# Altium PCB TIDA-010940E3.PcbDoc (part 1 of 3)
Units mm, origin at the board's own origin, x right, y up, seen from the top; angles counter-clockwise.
Board outline 71.12 x 63.5 mm, 2 copper layers (Top Layer, Bottom Layer), stack 1.382 mm thick; 136 components, 118 nets, 421 pads, 150 vias.
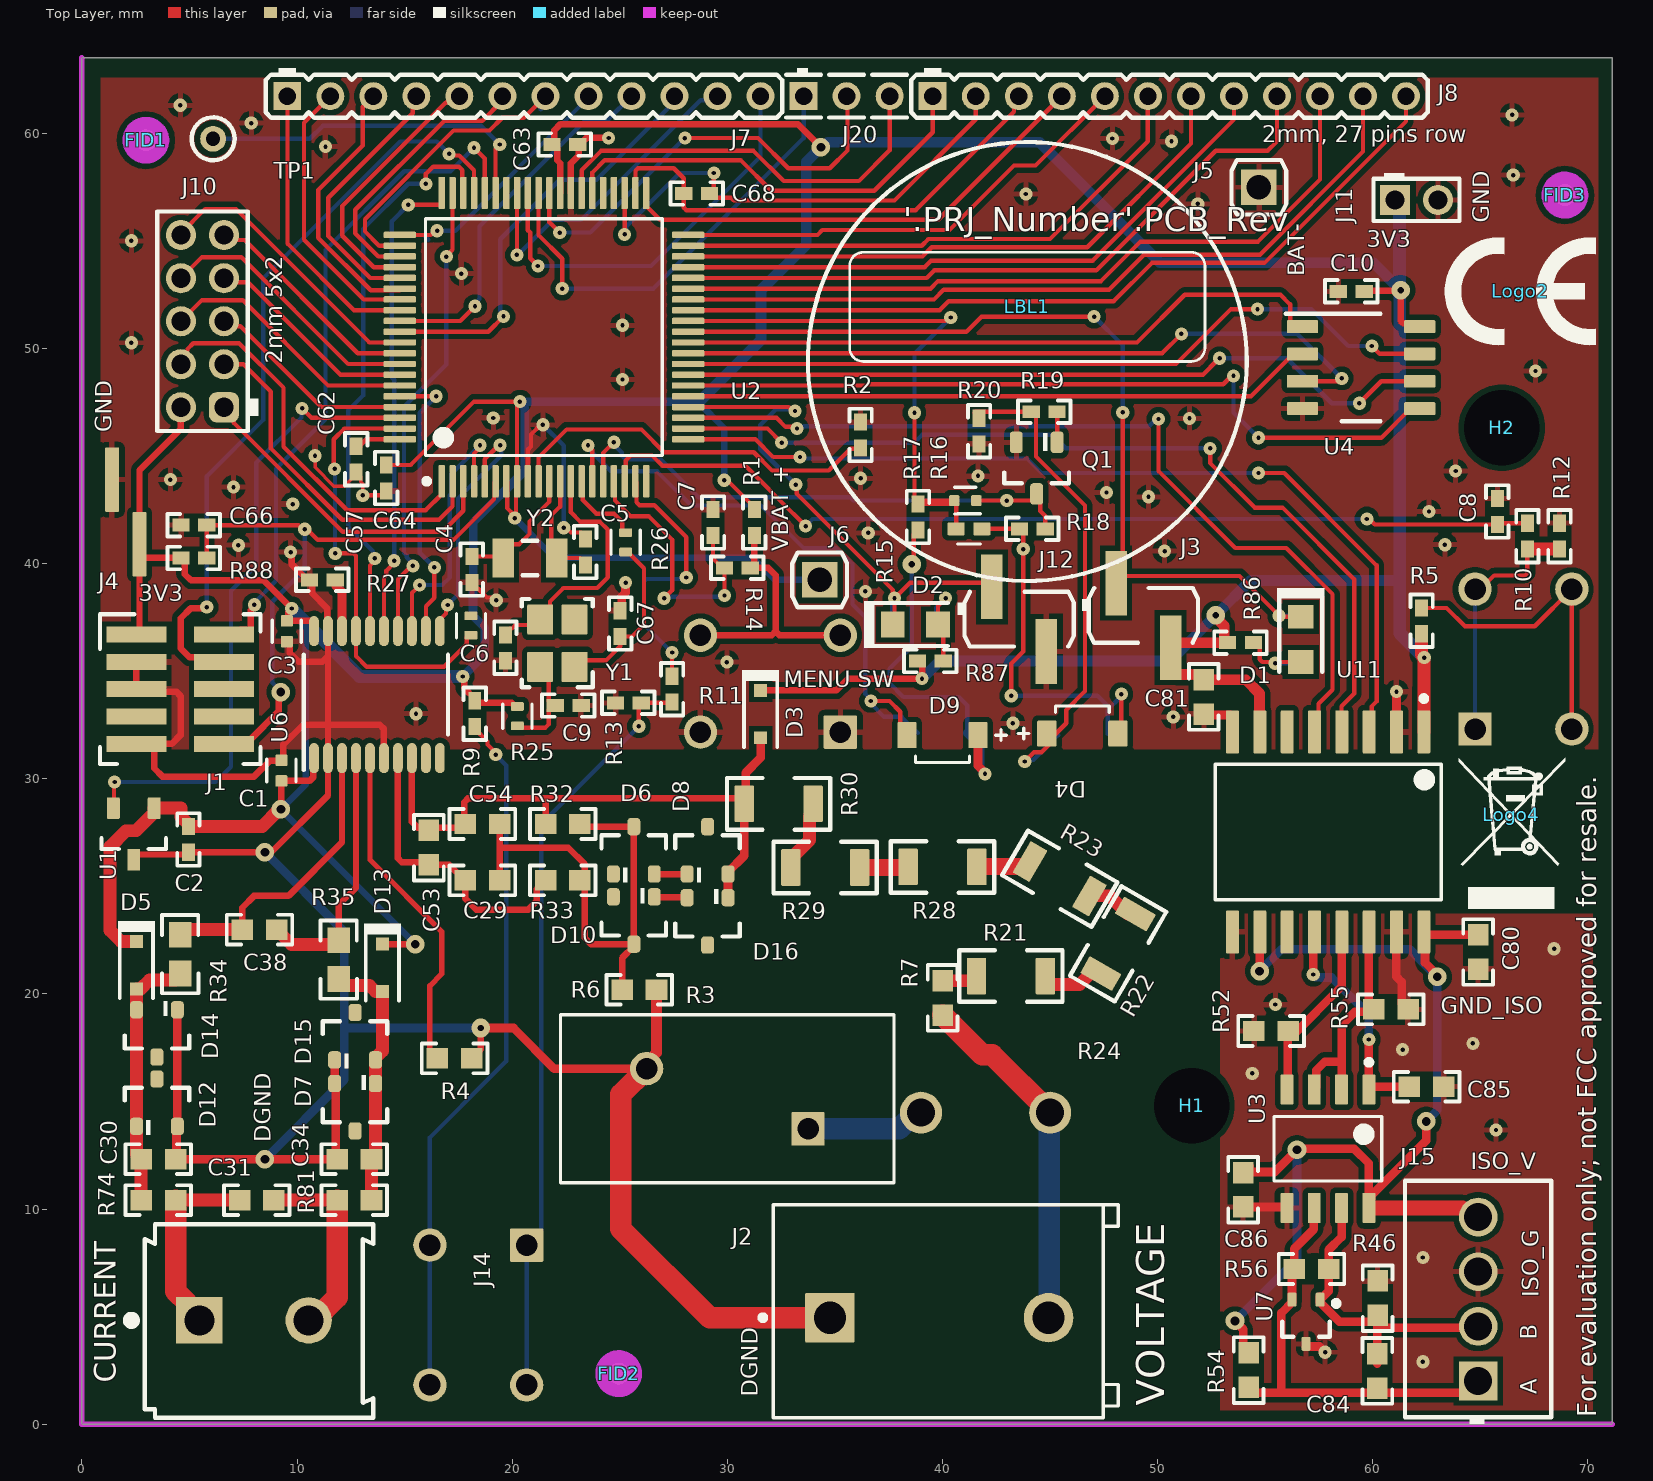
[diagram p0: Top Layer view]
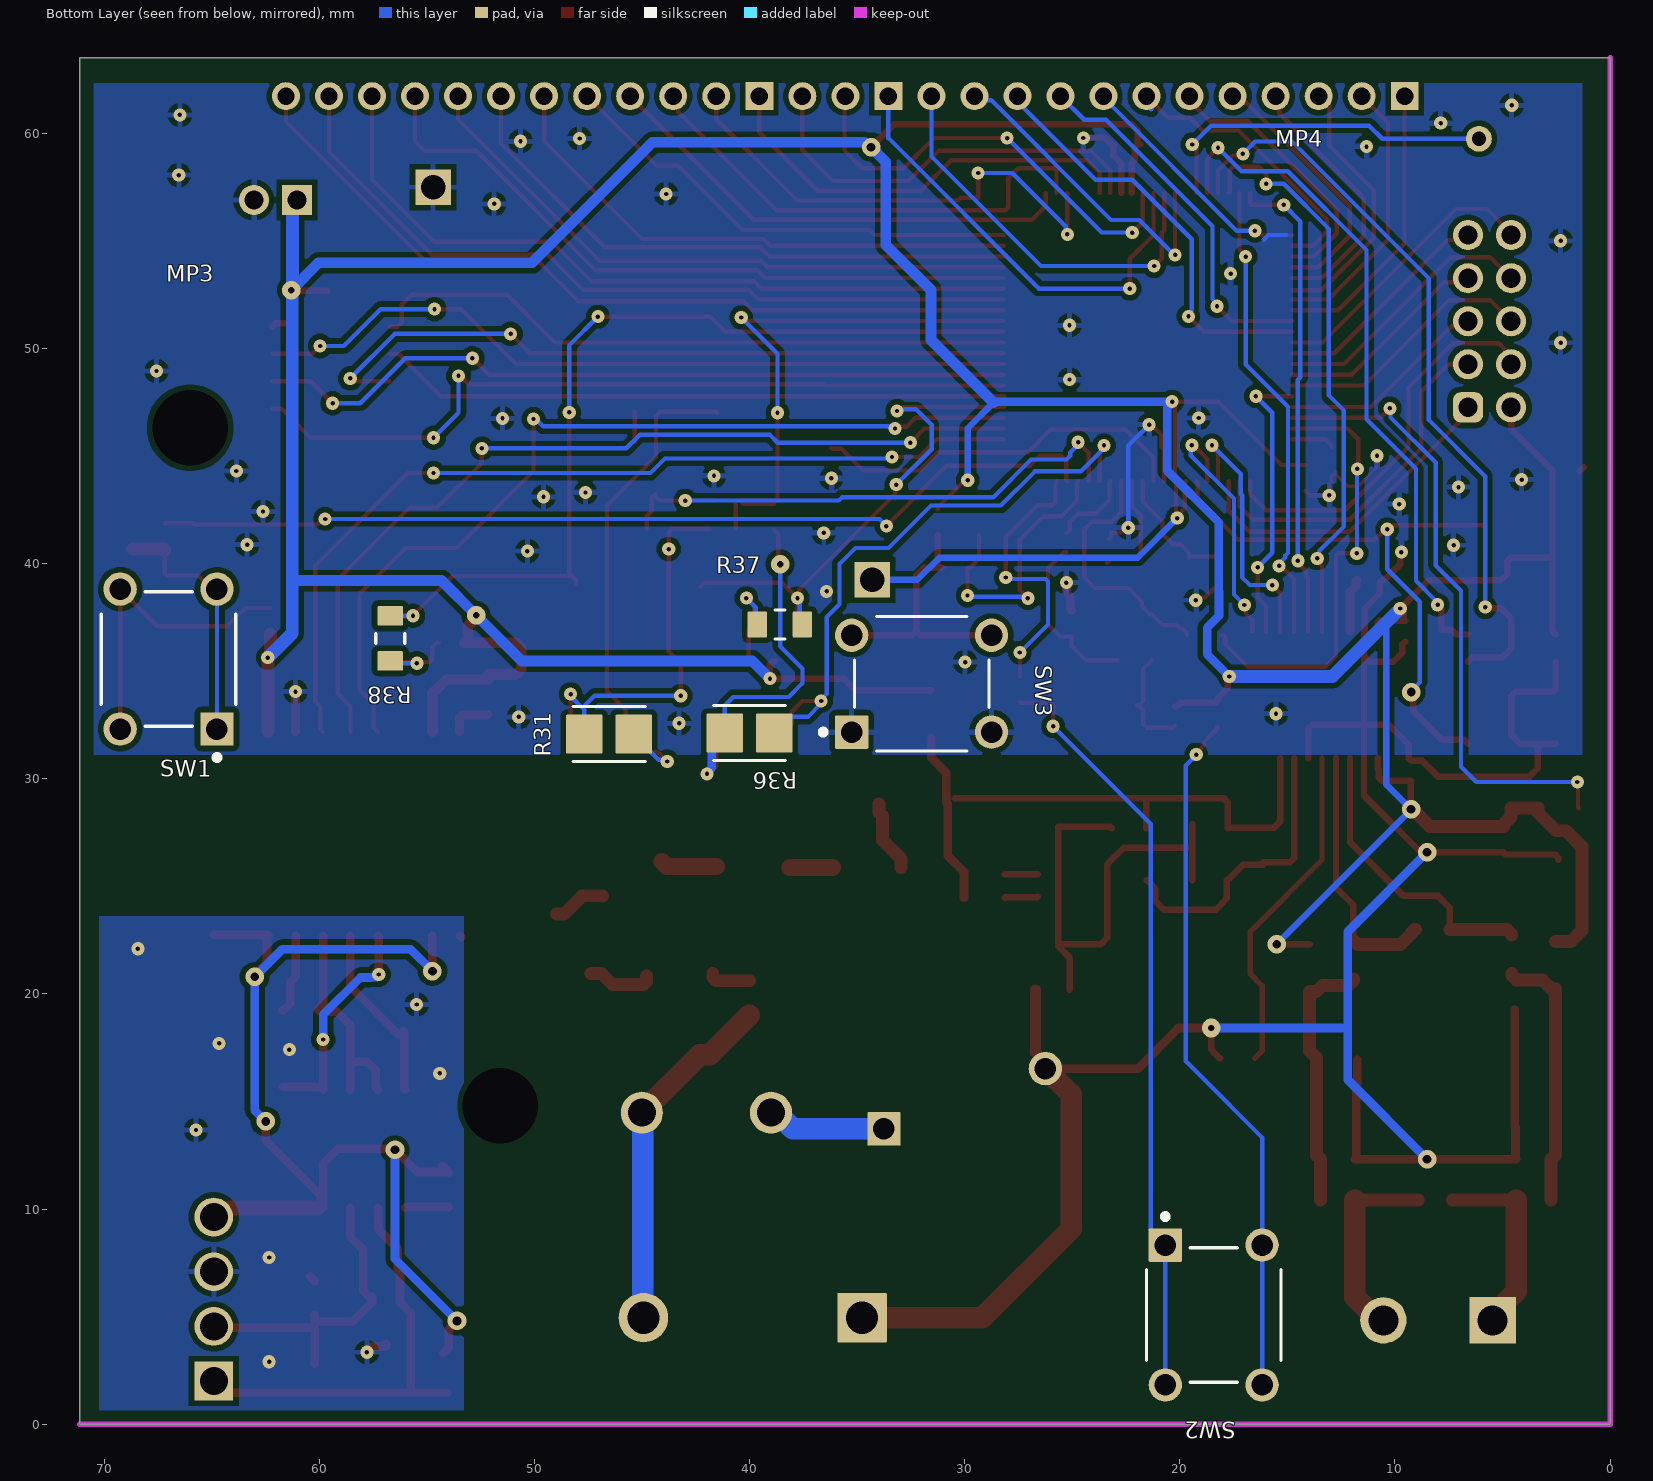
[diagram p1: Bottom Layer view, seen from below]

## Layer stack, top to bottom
Top Solder: solder mask 0.0102, Solder Resist, Dk 3.5
Top Layer: signal copper 0.0356
Dielectric 2: core 0.9906, Composite dielectric, Dk 4.8
Dielectric2: core 0.32, Composite dielectric, Dk 4.8
Bottom Layer: signal copper 0.0356
Bottom Solder: solder mask 0.0102, Solder Resist, Dk 3.5

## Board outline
0,0 0,63.5 71.12,63.5 71.12,0

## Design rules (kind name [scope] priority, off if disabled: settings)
AcuteAngle [All] p1: minimum=4.50000000000000E+0001 checktracksonly=FALSE
AssemblyTestPointUsage [All] p1: valid=2
BoardOutlineClearance BoardOutlineClearance_MountingHoles [OnCopper and InComponentClass('Mounting Holes')] p1: gap=1 ignorepadtopadclearanceinfootprint=FALSE
BoardOutlineClearance BoardOutlineClearance_Poly [OnCopper and IsPoly] p2: gap=0.635 ignorepadtopadclearanceinfootprint=FALSE
BoardOutlineClearance [OnCopper and Not InComponentClass('Logo') and not InComponentClass('FiducialMark') and not InRegion(1000,500,4000,800) and not InPoly] p3: gap=1.016 ignorepadtopadclearanceinfootprint=FALSE
Clearance Clearance_Keepouts [((IsTrack Or IsArc) And Not InPoly) And IsFree and IsKeepOut vs ((IsTrack Or IsArc) And Not InPoly) And IsFree and IsKeepOut] p1: gap=0 ignorepadtopadclearanceinfootprint=FALSE
Clearance Clearance_Poly [InPolygon] p2: gap=0.254 ignorepadtopadclearanceinfootprint=TRUE
Clearance Clearance_FiducialMark [IsKeepOut and InComponentClass('FiducialMark') vs IsPad and InComponentClass('FiducialMark')] p3: gap=0 ignorepadtopadclearanceinfootprint=FALSE
Clearance [All] p4: gap=0.18 ignorepadtopadclearanceinfootprint=TRUE
ComponentClearance ComponentClearance_BottomHW [All vs InComponentClass('Bottom Side Components')] p1: gap=0 collisioncheckmode=3 verticalgap=0 showdistances=FALSE
ComponentClearance ComponentClearance_Shunt [InComponentClass('Header') vs InComponentClass('Shunt')] p2: gap=0 collisioncheckmode=3 verticalgap=0 showdistances=FALSE
ComponentClearance ComponentClearance_MountingHoles_FiducialMarks [InComponentClass('Mounting Holes') vs InComponentClass('FiducialMark')] p3: gap=1.27 collisioncheckmode=3 verticalgap=0.254 showdistances=FALSE
ComponentClearance ComponentClearance_Logo [InComponentClass('Logo')] p4: gap=0.762 collisioncheckmode=3 verticalgap=0.254 showdistances=FALSE
ComponentClearance ComponentClearance_ScrewToNut [(HasFootprint('NY PMS 440 0025 PH')) vs (HasFootprint('Keystone_1902C'))] p5: gap=0.127 collisioncheckmode=3 verticalgap=0.254 showdistances=FALSE
ComponentClearance ComponentClearance_MountingHoles [InComponentClass('Mounting Holes')] p6: gap=2.54 collisioncheckmode=3 verticalgap=2540 showdistances=FALSE
ComponentClearance ComponentClearance_SmallPassives [HasFootprint('0201*') or HasFootprint('0402*') or HasFootprint('0508') or HasFootprint('0603*') or HasFootprint('0612') or HasFootprint('0805*') or HasFootprint('0815*') or HasFootprint('0830*') or HasFootprint('1206*') or HasFootprint('1210*') or HasFootprint('1808*') or HasFootprint('1812*') or HasFootprint('1825*') or HasFootprint('2010*') or HasFootprint('2220*') or HasFootprint('2225*') or HasFootprint('2512*') or HasFootprint('2728*') or HasFootprint('3518*') vs HasFootprint('0201*') or HasFootprint('0402*') or HasFootprint('0508') or HasFootprint('0603*') or HasFootprint('0612') or HasFootprint('0805*') or HasFootprint('0815*') or HasFootprint('0830*') or HasFootprint('1206*') or HasFootprint('1210*') or HasFootprint('1808*') or HasFootprint('1812*') or HasFootprint('1825*') or HasFootprint('2010*') or HasFootprint('2220*') or HasFootprint('2225*') or HasFootprint('2512*') or HasFootprint('2728*') or HasFootprint('3518*')] p7: gap=0.38 collisioncheckmode=3 verticalgap=0.254 showdistances=FALSE
ComponentClearance ComponentClearance_THtoSMT [IsThruComponent vs InComponentClass('Shunt')] p8: gap=0 collisioncheckmode=3 verticalgap=1 showdistances=FALSE
ComponentClearance ComponentClearance_LCDtoSMT [IsThruComponent vs InComponentClass('Shunt')] p9: gap=0 collisioncheckmode=3 verticalgap=1 showdistances=FALSE
ComponentClearance ComponentClearance_THtoTH [IsThruComponent vs IsThruComponent] p10: gap=0.508 collisioncheckmode=3 verticalgap=0.762 showdistances=FALSE
ComponentClearance [All] p11: gap=0.508 collisioncheckmode=3 verticalgap=0.254 showdistances=FALSE
DiffPairsRouting [All] p1: maxlimit=2.54 minlimit=0.254 mostfreqgap=0.254 toplayer_minwidth=0.381 toplayer_maxwidth=0.381 toplayer_prefwidth=0.381 bottomlayer_minwidth=0.381 bottomlayer_maxwidth=0.381 bottomlayer_prefwidth=0.381 maxuncoupledlength=25.4
FabricationTestPointUsage TestPointUsage [All] p1: valid=2 allowmultiple=FALSE
FabricationTestpoint Testpoint [All] p1: side=3 testpointundercomponent=TRUE minsize=1.016 maxsize=2.54 preferedsize=1.524 minholesize=0 maxholesize=1.016 preferedholesize=0.813 testpointgrid=0.025 allowsidetop=TRUE allowsidebottom=TRUE usegrid=TRUE gridtolerance=0
FanoutControl Fanout_LCC [IsLCC] p1: bgadir=Out bgaviamode=Centered fanoutstyle=Auto fanoutdirection=Alternating viagrid=0.025 // Fanout_LCC (Default Rule)
FanoutControl Fanout_BGA [IsBGA] p2: bgadir=Out bgaviamode=Centered fanoutstyle=Auto fanoutdirection=Alternating viagrid=0.025 // Fanout_BGA (Default Rule)
FanoutControl Fanout_Default [All] p4: bgadir=Out bgaviamode=Centered fanoutstyle=Auto fanoutdirection=Alternating viagrid=0.025 // Fanout_Default (Default Rule)
FanoutControl Fanout_Small [(CompPinCount < 5)] p5: bgadir=Out bgaviamode=Centered fanoutstyle=Auto fanoutdirection=OutThenIn viagrid=0.025 // Fanout_Small (Default Rule)
Height [All] p1: minheight=0 maxheight=29 prefheight=12.7
HoleSize [All] p1: absolutevalues=TRUE maxlimit=6.375 minlimit=0.2 maxpercent=80.000 minpercent=20.000
MinimumAnnularRing MinimumAnnularRing_ThermalPadVias [IsVia and InAnyComponent] p1: minimumring=0.15
MinimumAnnularRing [All] p2: minimumring=0.188
MinimumSolderMaskSliver MinimumSolderMaskSliver_Logo [InComponentClass('Logo') vs InComponentClass('Logo')] p1: minsoldermaskwidth=0.018
MinimumSolderMaskSliver [All] p2: minsoldermaskwidth=0.094
PlaneConnect [All] p1: pad.planeconnectstyle=Relief pad.reliefexpansion=0.254 pad.reliefentries=4 pad.reliefconductorwidth=0.254 pad.reliefairgap=0.254 via.planeconnectstyle=Direct via.reliefexpansion=0.254 via.reliefentries=4 via.reliefconductorwidth=0.254 via.reliefairgap=0.254
PolygonConnect PolygonConnect_largePoly [All vs IsNamedPolygon('TOP_LAYER_DGNDA_P032') or IsNamedPolygon('BOTTOM_LAYER_DGNDA_P034')   or IsNamedPolygon('TOP_LAYER_HGNDB_P040')     or IsNamedPolygon('BOTTOM_LAYER_HGNDB_P042')   or IsNamedPolygon('TOP_LAYER_DGNDB_P033') or IsNamedPolygon('BOTTOM_LAYER_DGNDB_P035')] p1: thpad.connectstyle=Relief thpad.reliefconductorwidth=0.254 thpad.reliefentries=4 thpad.polygonreliefangle="90 Angle" thpad.airgapwidth=0.254 smdpad.connectstyle=Relief smdpad.reliefconductorwidth=0.254 smdpad.reliefentries=4 smdpad.polygonreliefangle="90 Angle" smdpad.airgapwidth=0.254 via.connectstyle=Direct via.reliefconductorwidth=0.254 via.reliefentries=4 via.polygonreliefangle="90 Angle" via.airgapwidth=0.254
PolygonConnect PolygonConnect_smallHGNDpoly [All vs IsPolygon and InNet('HGNDA')  or  IsNamedPolygon('TOP_LAYER_HGNDB_P024') or IsNamedPolygon('TOP_LAYER_HGNDB_P037')  or IsNamedPolygon('TOP_LAYER_HGNDB_P039')  or IsNamedPolygon('BOTTOM_LAYER_HGNDB_P043')] p2: connectstyle=Direct reliefconductorwidth=0.254 reliefentries=4 polygonreliefangle="90 Angle" airgapwidth=0.254
PolygonConnect PolygonConnect_DVDDpoly [All vs IsNamedPolygon('TOP_LAYER_ADC_DVDDA_P029') or IsNamedPolygon('TOP_LAYER_ADC_DVDDB_P029')] p3: connectstyle=Direct reliefconductorwidth=0.254 reliefentries=4 polygonreliefangle="90 Angle" airgapwidth=0.254
PolygonConnect [All] p4: connectstyle=Relief reliefconductorwidth=0.254 reliefentries=4 polygonreliefangle="90 Angle" airgapwidth=0.254
RoutingVias ThermalPadVias [IsVia and InAnyComponent] p1: holewidth=0.2 width=0.5 viastyle="Through Hole" minholewidth=0.2 minwidth=0.5 maxholewidth=0.33 maxwidth=0.6
RoutingVias [All] p2: holewidth=0.406 width=0.864 viastyle="Through Hole" minholewidth=0.2 minwidth=0.61 maxholewidth=1.016 maxwidth=1.651
SilkToBoardRegionClearance [Not ((IsComment or IsDesignator) And (Hide <> 'False')) and not InRegion(1000,500,4000,800)] p1:
SilkToSilkClearance SilkToSilkClearance_Pb-FreeLogo [(HasFootprint('Pb-Free_Overlay_Medium') OR HasFootprint('Pb-Free_Overlay_Small')) vs (HasFootprint('Pb-Free_Overlay_Medium') OR HasFootprint('Pb-Free_Overlay_Small'))] p1: silktosilkclearance=0
SilkToSilkClearance [All] p2: silktosilkclearance=0.1
SilkToSolderMaskClearance SilkToComponentPadClearance [(IsPad or IsFill or IsRegion) and InAnycomponent] p1: minsilkscreentomaskgap=0.12 clearancetoexposedcopper=TRUE
SilkToSolderMaskClearance "Silk to Solder Mask Opening" [All] p2: minsilkscreentomaskgap=0.1 clearancetoexposedcopper=FALSE
SolderMaskExpansion [All] p1: expansion=0.05 istentingtop=FALSE
SupplyNets "Schematic Supply Nets_3" [InNet('VCC_ISO_RS')] p1: voltage=0.000
SupplyNets "Schematic Supply Nets_2" [InNet('GND_ISO_RS')] p2: voltage=0.000
SupplyNets "Schematic Supply Nets_1" [InNet('DGND')] p3: voltage=0.000
SupplyNets "Schematic Supply Nets" [InNet('DVDD')] p4: voltage=0.000
UnRoutedNet [All] p1: checkbadconnections=TRUE
Width [All] p1: maxlimit=2.54 minlimit=0.152 preferedwidth=0.254 checkconnectedcopper=TRUE
13 further rules are at their usual default settings.

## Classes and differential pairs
component class TIDA-010940E3-Interfaces: C80 C81 C84 C85 C86 D4 D9 J3 J12 J15 Q1 R15 R16 R17 R18 R19 R20 R31 R36 R46 R52 R54 R55 R56 U3 U7 U11
component class TIDA-010940E3-1P_ADS131M03: C1 C3 C29 C30 C31 C34 C38 C53 C54 C57 D3 D5 D6 D7 D8 D10 D12 D13 D14 D15 D16 J2 J14 R3 R4 R6 R7 R21 R22 R23 R24 R28 R29 R30 R32 R33 R34 R35 R74 R81 U6
component class TIDA-010940E3-Hardware: !PCB1 FID1 FID2 FID3 H1 H2 LBL1 Logo2 Logo3 Logo4 MP1 MP2 MP3 MP4 ZZ1 ZZ2 ZZ3 ZZ4
component class Label: LBL1
component class FiducialMark: FID1 FID2 FID3
component class TIDA-010940E3-M0L228_80p: C2 C4 C5 C6 C7 C8 C9 C10 C62 C63 C64 C66 C67 C68 D1 D2 J1 J4 J5 J6 J7 J8 J10 J11 J20 R1 R2 R5 R9 R10 R11 R12 R13 R14 R25 R26 R27 R37 R38 R86 R87 R88 SW1 SW2 SW3 TP1 U1 U2 U4 Y1 Y2
component class AssemblyNote: C10A C11A C12A C13A ZZ1 ZZ2 ZZ3 ZZ4
component class Header: J3 J4 J5 J6 J7 J8 J10 J11 J12 J20

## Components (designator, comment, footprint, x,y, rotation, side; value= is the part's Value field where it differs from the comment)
C1 "GMC04X7R105K10NT" FP-GMC04X7R105K10NT_0402-MFG 9.273,30.378 r270 top value=1µF
C2 "GRM155R71E104KE14D" 0402 4.953,27.178 r270 top value=0.1uF
C3 "GMC04X7R105K10NT" FP-GMC04X7R105K10NT_0402-MFG 9.525,36.855 r90 top value=1µF
C4 "GRM1555C1H220JA01D" 0402 18.125,39.725 r90 top value=22pF
C5 "GRM1555C1H220JA01D" 0402 23.4,40.539 r270 top value=22pF
C6 "GRM1555C1H150JA01D" 0402 19.685,36.084 r270 top value=15pF
C7 "0402YC101KAT2A" 0402 29.337,41.91 r90 top value=100pF
C8 "0402YC101KAT2A" 0402 65.786,42.418 r90 top value=100pF
C9 "GRM155R61C474KE01" 0402 22.606,33.401 r0 top value=0.47uF
C10 "GRM155R71E104KE14D" 0402 58.997,52.652 r180 top value=0.1uF
C29 "GRM188R71C333KA01D" 0603 18.617,25.273 r180 top value=0.033uF
C30 "GRM188R71C333KA01D" 0603 3.556,12.319 r0 top value=0.033uF
C31 "06035C104KAT2A" 0603 8.128,10.414 r0 top value=0.1uF
C34 "GRM188R71C333KA01D" 0603 12.662,12.319 r0 top value=0.033uF
C38 "GRM188R71C333KA01D" 0603 8.255,22.987 r0 top value=0.033uF
C53 "C0603C472J1GAC7867" 0603 16.129,26.797 r270 top value=4700pF
C54 "GRM188R71C333KA01D" 0603 18.617,27.896 r0 top value=0.033uF
C57 "CL05B224KO5NNNC" 0402 11.176,39.243 r0 top value=0.22uF
C62 "GRM155R61C474KE01" 0402 12.75,44.85 r90 top value=0.47uF
C63 "GRM155R61A106ME11D" 0402 22.45,59.475 r180 top value=10uF
C64 "GRM155R61E105KE11D" 0402 14.149,43.978 r270 top value=1uF
C66 "GRM155R61A102KA01D" 0402 5.207,41.783 r180 top value=1000pF
C67 "GRM1555C1H150JA01D" 0402 25.019,37.211 r90 top value=15pF
C68 "GRM155R61C474KE01" 0402 28.575,57.2 r0 top value=0.47uF
C80 "C0603X104K3RACTU" 0603 64.897,21.946 r270 top value=0.1uF
C81 "C0603X104K3RACTU" 0603 52.142,33.801 r270 top value=0.1uF
C84 "CGA3E2C0G1H100D080AA" 0603 60.209,2.477 r90 top value=10pF
C85 "CGA3E2C0G1H100D080AA" 0603 62.5,15.685 r180 top value=10pF
C86 "CGA3E2X8R1E104K080AA" 0603 53.975,10.897 r270 top value=0.1uF
D1 "150080VS75000" WL-SMCW_Green_0805 56.65,36.475 r270 top value="Bright Green"
D2 "150080VS75000" WL-SMCW_Green_0805 38.745,37.166 r0 top value="Bright Green"
D3 "BAT54HT1G" SOD-323 31.547,33.002 r270 top value=30V
D4 "VSMY2853SLX01" FP-VSMY2853SLX01_SMT_LED_2MM30_2MM55-MFG 46.5,32 r180 top
D5 "BAT54HT1G" SOD-323 2.54,21.336 r270 top value=30V
D6 "BAV199-TP" SOT-23L 25.654,26.67 r90 top value=70V
D7 "BAV199-TP" SOT-23L 12.7,14.732 r270 top value=70V
D8 "BAV199-TP" SOT-23L 29.083,26.67 r90 top value=70V
D9 "VSMY2853SLX01" FP-VSMY2853SLX01_SMT_LED_2MM30_2MM55-MFG 40,32.125 r0 top
D10 "BAV199-TP" SOT-23L 25.654,23.411 r270 top value=70V
D12 "BAV199-TP" SOT-23L 3.49,14.943 r90 top value=70V
D13 "BAT54HT1G" SOD-323 13.97,21.209 r270 top value=30V
D14 "BAV199-TP" SOT-23L 3.49,18.161 r270 top value=70V
D15 "BAV199-TP" SOT-23L 12.7,18.034 r90 top value=70V
D16 "BAV199-TP" SOT-23L 29.083,23.368 r270 top value=70V
FID1 "Fiducial" Fiducial10-20 2.975,59.675 r0 top
FID2 "Fiducial" Fiducial10-20 24.95,2.35 r0 top
FID3 "Fiducial" Fiducial10-20 68.925,57.125 r90 top
H1 "3.5 MM HOLE" 3_5MM_HOLE 51.583,14.806 r0 top
H2 "3.5 MM HOLE" 3_5MM_HOLE 65.994,46.307 r0 top locked
J1 "FTSH-105-01-L-DV-K" Samtec_FTSH-105-01-x-DV-K 4.572,34.163 r0 top
J2 "691216610002" FP-691216610002_TERM_BLK_2-MFG 40.15,5.25 r0 top
J3 "61000218321" Wurth_61000218321 49.336,37.592 r0 top
J4 "M50-3630242" Harwin_M50-3630242 2.045,42.4 r0 top
J5 "61300111121" WURTH_61300111121 54.704,57.489 r0 top
J6 "61300111121" WURTH_61300111121 34.29,39.242 r0 top
J7 "M22-2511205" Harwin_M22-2511205 20.546,61.722 r0 top
J8 "M22-2511205" Harwin_M22-2511205 50.546,61.722 r0 top
J10 "MTMM-105-15-L-D-150" Samtec_MTMM-105-15-x-D-150 5.604,51.262 r180 top
J11 "TMM-102-01-F-S" Samtec_TMM-102-01-F-S 62.031,56.898 r0 top
J12 "61000218321" Wurth_61000218321 43.561,37.413 r0 top
J14 "282841-2" TEC_282841-2 8.001,4.826 r0 top
J15 "OSTVN04A150" On-Shore_OSTVN04A150 64.897,5.817 r90 top
J20 "PTT-103-01-L-S" Samtec_PTT-103-01-x-S 35.543,61.722 r0 top
LBL1 "THT-14-423-10" Label_650x200 43.942,51.929 r0 top
Logo2 "CE Mark" CE_Mark_5mm 66.85,52.65 r0 top
Logo3 "FCC disclaimer" FCC_disclaimer 79.75,-3.975 r90 top
Logo4 "WEEE logo" WEEE_Minimum 66.425,28.325 r0 top
MP1 "SJ5076" FP-SJ5076_BUMPER_CYLIN-MFG -9.275,8.4 r180 bottom
MP2 "SJ5076" FP-SJ5076_BUMPER_CYLIN-MFG 80.425,8.4 r180 bottom
MP3 "SJ5076" FP-SJ5076_BUMPER_CYLIN-MFG 60.356,51.607 r180 bottom
MP4 "SJ5076" FP-SJ5076_BUMPER_CYLIN-MFG 11.375,54.752 r180 bottom
Q1 "BC848CLT1G" SOT-23 44.377,44.436 r270 top value="30 V"
R1 "RC0402FR-07220KL" 0402 31.256,41.909 r90 top value=220k
R2 "RG1005P-104-B-T5" 0402 36.195,45.974 r270 top value=100k
R3 "B72214S2461K101" FP-B72214S2461K101_RADIAL-MFG 30,15.125 r180 top
R4 "ERJ-3GEY0R00V" 0603 17.325,17 r180 top value=0
R5 "ERJ-2RKF1002X" 0402 62.267,37.338 r270 top value=10.0k
R6 "ERJ-3GEY0R00V" 0603 25.908,20.193 r180 top value=0
R7 "ERJ-3GEY0R00V" 0603 40.005,19.812 r90 top value=0
R9 "ERJ-2RKF1002X" 0402 18.26,33.02 r90 top value=10.0k
R10 "RC0402FR-072K2L" 0402 67.183,41.275 r90 top value=2.20k
R11 "RC0402FR-072K2L" 0402 27.432,34.163 r90 top value=2.20k
R12 "CRCW04024M70JNED" 0402 68.674,41.275 r270 top value=4.7Meg
R13 "CRCW04024M70JNED" 0402 25.401,33.528 r0 top value=4.7Meg
R14 "CRCW04021K00JNED" 0402 30.466,39.8 r180 top value=1.0k
R15 "CR0402-10W-000T" FP-CR0402-10W-000T_0402-MFG 41.233,41.614 r180 top value=0uΩ
R16 "ERA-2ARB8061X" FP-ERA-2ARB8061X_0402-MFG 41.058,42.926 r180 top value=8.06k
R17 "RC0402FR-07820RL" 0402 38.862,42.164 r90 top value=820
R18 "RC0402FR-071KL" 0402 44.177,41.614 r180 top value=1.00k
R19 "ERJ-2RKF2200X" 0402 44.727,47.053 r180 top value=220
R20 "CRCW0402820RJNED" 0402 41.7,46.15 r90 top value=820
R21 "TNPV1206330KBEEN" TNPV1206 43.18,20.828 r180 top value=330k
R22 "TNPV1206330KBEEN" TNPV1206 48.163,22.325 r240 top value=330k
R23 "TNPV1206330KBEEN" TNPV1206 45.45,25.35 r150 top value=330k
R24 "AC05000004700JAC00" AC05_Vert 45,14.478 r180 top value=470
R25 "0" FP-5113_0402-MFG 20.24,32.906 r90 top
R26 "0" FP-5113_0402-MFG 25.273,40.988 r90 top
R27 "0" FP-5113_0402-MFG 18.082,37.119 r270 top
R28 "TNPV1206330KBEEN" TNPV1206 40,25.9 r0 top value=330k
R29 "TNPV1206330KBEEN" TNPV1206 34.55,25.875 r0 top value=330k
R30 "TNPV1206330KBEEN" TNPV1206 32.385,28.829 r180 top value=330k
R31 "PMR18EZPJ000" FP-PMR18EZPJ000_1206-MFG 46.525,32.075 r0 bottom value=0
R32 "RC0603FR-071KL" 0603 22.352,27.896 r180 top value=1.00k
R33 "RC0603FR-071KL" 0603 22.35,25.275 r180 top value=1.00k
R34 "RC0603FR-071KL" 0603M 4.572,21.844 r90 top value=1.00k
R35 "RC0603FR-071KL" 0603M 11.938,21.59 r90 top value=1.00k
R36 "PMR18EZPJ000" FP-PMR18EZPJ000_1206-MFG 40,32.125 r0 bottom value=0
R37 "RC0805FR-070RL" FP-RC0805FR-070RL_0805-MFG 38.591,37.166 r0 bottom value=0
R38 "RC0805FR-070RL" FP-RC0805FR-070RL_0805-MFG 56.7,36.525 r270 bottom value=0
R46 "CRCW0603100KJNEA" 0603 60.219,5.858 r270 top value=100k
R52 "CRCW06034K70JNEA" 0603 55.272,18.275 r180 top value=4.7k
R54 "CRCW0603100KJNEA" 0603 54.229,2.515 r90 top value=100k
R55 "CRCW06034K70JNEA" 0603 60.838,19.279 r0 top value=4.7k
R56 "RT0603DRE07120RL" 0603 57.15,7.214 r180 top value=120
R74 "ERJ-3GEY0R00V" 0603 3.556,10.414 r180 top value=0
R81 "ERJ-3GEY0R00V" 0603 12.662,10.414 r0 top value=0
R86 "RC0402FR-071KL" 0402 53.848,36.322 r180 top value=1.00k
R87 "RC0402FR-071KL" 0402 39.436,35.471 r180 top value=1.00k
R88 "CRCW040247K0JNED" 0402 5.207,40.259 r180 top value=47k
SW1 "TL1105DF250Q" FP-TL1105DF250Q_PTH_SW_6MM0_6MM0-MFG 67,35.56 r270 bottom
SW2 "TL1105DF250Q" FP-TL1105DF250Q_PTH_SW_6MM0_6MM0-MFG 18.425,5.075 r90 bottom locked
SW3 "TL1105DF250Q" FP-TL1105DF250Q_PTH_SW_6MM0_6MM0-MFG 32,34.417 r0 bottom
TP1 "3154-0-00-15-00-00-03-0" Mill-Max_3154-0-00-15-00-00-03-0 6.1,59.74 r0 top
U1 "DRV5032ZEDBZR" DBZ0003A_N 2.413,27.432 r270 top locked
U2 "MSPM0L2228TPN" PN0080A-MFG 21.478,50.524 r90 top locked
U3 "THVD1400D" D0008B-MFG 57.912,12.802 r270 top
U4 "W25Q80JVSNIQ" SOIC-8 59.456,49.107 r0 top
U6 "ADS131M03IPWR" PW0020A_N 13.716,33.909 r90 top locked
U7 "TPD2E007DCKR" DCK0003A_L 56.896,4.763 r270 top
U11 "ISO6731DWR" DW0016A-MFG 57.925,27.525 r270 top locked
Y1 "FA-238 16.3840MB-K" Epson_FA-238 22.1,36.3 r180 top
Y2 "X1A0001410014" Epson_FC-135 20.828,40.259 r180 top
ZZ1 "This Assembly Note is for PCB labels only" AssemblyNoteLabel 120.015,3.048 r90 top
ZZ2 "These assemblies are ESD sensitive, ESD precautions shall be observed." AssemblyNote 111.76,68.072 r270 top
ZZ3 "These assemblies must be clean and free from flux and all contaminants. Use of no clean flux is not acceptable." AssemblyNote 4.191,134.493 r0 top
ZZ4 "These assemblies must comply with workmanship standards IPC-A-610 Class 2, unless otherwise specified." AssemblyNote 115.189,86.106 r270 top

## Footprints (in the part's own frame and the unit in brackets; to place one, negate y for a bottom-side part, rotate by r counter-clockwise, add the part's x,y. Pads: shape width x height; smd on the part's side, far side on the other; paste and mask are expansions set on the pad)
3_5MM_HOLE [mm]
  round 3.2 hole 3.5 unplated mask+0.102: ""(0,0)
0402 [mm] "0402 from SM-752 data"
  rect 0.8x0.6 smd: 1(-0.6,0) 2(0.6,0)
  silkscreen extent -1.22,-0.52 1.22,0.52, body extent -0.55,-0.3 0.55,0.3, height 0.6
0603 [mm] "0603 from SM-752 data"
  rect 1x0.95 smd: 1(-0.8,0) 2(0.8,0)
  silkscreen extent -1.52,-0.69 1.52,0.69, body extent -0.87,-0.47 0.87,0.47, height 1
0603M [mm] "0603 from SM-752 data"
  rect 1.2x1.05 smd: 1(-0.9,0) 2(0.9,0)
  silkscreen extent -1.82,-0.84 1.82,0.84, body extent -0.87,-0.47 0.87,0.47, height 1
AC05_Vert [mm] "TH, 2-Leads, Dia 7.5mm"
  round 1.95 hole 1.3: 1(0,0) 2(6,0)
  body extent -3.75,-3.75 6.4,3.75, height 26.88
AssemblyNote [mm] "Assembly Note"
AssemblyNoteLabel [mm] "Assembly Note for PCB Labels"
CE_Mark_5mm [mm] "Minimum text height for CE Mark"
  silkscreen extent -3.5,-2.5 3.5,2.5
D0008B-MFG [mm]
  rrect17% 1.4x0.6 smd paste+0 mask+0: 1(-2.75,1.905) 2(-2.75,0.635) 3(-2.75,-0.635) 4(-2.75,-1.905) 5(2.75,-1.905) 6(2.75,-0.635) 7(2.75,0.635) 8(2.75,1.905)
  silkscreen extent -4.14,-2.5 1.5,2.5, body extent -3.55,-2.75 3.55,2.75, height 0.25
DBZ0003A_N [mm] "SOT23, 3-Leads, Body 2.9x1.3mm, Pitch 0.95mm, Lead Span 2.4mm, IPC Medium Density"
  rrect17% 1x0.6 smd: 1(-1.2,0.95) 2(-1.2,-0.95) 3(1.2,0)
  silkscreen extent 0.2,-1.5 0.7,1.5, body extent -1.26,-1.46 1.26,1.46, height 0.98
DCK0003A_L [mm] "SOT23, 3-Leads, Body 2.0x1.25mm, Pitch 0.65mm, Lead Span 2.1mm, IPC High Density"
  rrect25% 0.65x0.4 smd: 1(-1.025,0.65) 2(-1.025,-0.65) 3(1.025,0)
  silkscreen extent -0.97,-1.1 0.7,1.53, body extent -1.06,-1 1.06,1, height 1.1
DW0016A-MFG [mm]
  rrect17% 2x0.6 smd paste+0 mask+0: 1(-4.65,4.445) 2(-4.65,3.175) 3(-4.65,1.905) 4(-4.65,0.635) 5(-4.65,-0.635) 6(-4.65,-1.905) 7(-4.65,-3.175) 8(-4.65,-4.445) 9(4.65,-4.445) 10(4.65,-3.175) 11(4.65,-1.905) 12(4.65,-0.635) 13(4.65,0.635) 14(4.65,1.905) 15(4.65,3.175) 16(4.65,4.445)
  silkscreen extent -6.32,-5.25 3.15,5.25, body extent -5.75,-5.35 5.75,5.35, height 0.25
Epson_FA-238 [mm] "SMD, 4-Leads, Body 3.2x2.5mm"
  rrect8% 1.2x1.4 smd: 1(-0.8,1.1) 2(-0.8,-1.1) 3(0.8,-1.1) 4(0.8,1.1)
  silkscreen extent -1.65,-2.05 1.65,2.05, body extent -1.3,-1.65 1.3,1.65, height 0.7
Epson_FC-135 [mm] "SMD, 2-Leads, Body 3.2x1.5mm"
  rect 1x1.8 smd: 1(-1.25,0) 2(1.25,0)
  silkscreen extent -0.35,-0.8 0.35,0.8, body extent -1.65,-0.8 1.65,0.8, height 0.9
FCC_disclaimer [mm]
Fiducial10-20 [mm]
  round 1 smd mask+0.5: 1(0,0)
  Top Layer keep-out circle w1.178: c0,0 r0.5
FP-5113_0402-MFG [mm]
  rrect25% 0.4x0.6 smd paste+0 mask+0: 1(-0.45,0) 2(0.45,0)
  silkscreen extent -0.57,-0.67 0.57,0.67, body extent -0.75,-0.42 0.75,0.42, height 0.25
FP-691216610002_TERM_BLK_2-MFG [mm]
  rrect4% 2.3x2.3 hole 1.5 paste-2539.97 mask+0: 1(-5.38,-0.3)
  round 2.3 hole 1.5 paste-2539.97 mask+0: 2(4.78,-0.3)
  silkscreen extent -8.62,-4.95 8.02,4.95, body extent -8.12,-5.05 8.12,5.05, height 0.25
FP-B72214S2461K101_RADIAL-MFG [mm]
  rrect6% 1.55x1.55 hole 1 paste-2539.97 mask+0: 1(-3.75,1.4)
  round 1.55 hole 1 paste-2539.97 mask+0: 2(3.75,-1.4)
  silkscreen extent -7.75,-3.9 7.75,3.9, body extent -7.85,-4 7.85,4, height 0.25
FP-CR0402-10W-000T_0402-MFG [mm]
  rrect17% 0.8x0.6 smd paste+0 mask+0: 1(-0.6,0) 2(0.6,0)
  silkscreen extent -0.53,-0.7 0.53,0.7, body extent -1.1,-0.4 1.1,0.4, height 0.25
FP-ERA-2ARB8061X_0402-MFG [mm]
  rrect21% 0.475x0.5 smd paste+0 mask+0: 1(-0.512,0) 2(0.512,0)
  silkscreen extent -0.5,-0.63 0.5,0.63, body extent -0.85,-0.4 0.85,0.4, height 0.25
FP-GMC04X7R105K10NT_0402-MFG [mil]
  rrect19% 21x22 smd paste+0 mask+0: 1(-19,0) 2(19,0)
  silkscreen extent -21,-27 21,27, body extent -33,-15 33,15, height 10
FP-PMR18EZPJ000_1206-MFG [mm]
  rrect6% 1.7x1.8 smd paste+0 mask+0: 1(-1.15,0) 2(1.15,0)
  silkscreen extent -1.68,-1.28 1.68,1.28, body extent -1.6,-0.8 1.6,0.8, height 0.42
FP-RC0805FR-070RL_0805-MFG [mm]
  rrect11% 0.9x1.2 smd paste+0 mask+0: 1(-1.05,0) 2(1.05,0)
  silkscreen extent -0.23,-0.67 0.23,0.67, body extent -1,-0.63 1,0.63, height 0.6
FP-SJ5076_BUMPER_CYLIN-MFG [mm]
  body extent -4,-4 4,4, height 2.8
FP-TL1105DF250Q_PTH_SW_6MM0_6MM0-MFG [mm]
  rrect6% 1.55x1.55 hole 1 paste-2539.97 mask+0: 1(3.25,2.25)
  round 1.55 hole 1 paste-2539.97 mask+0: 2(-3.25,2.25) 3(3.25,-2.25) 4(-3.25,-2.25)
  silkscreen extent -3.13,-3.13 4.7,3.13, body extent -3.95,-3 3.95,3, height 13.25
FP-VSMY2853SLX01_SMT_LED_2MM30_2MM55-MFG [mm]
  rrect11% 0.9x1.2 smd paste+0 mask+0: 1(-1.65,-0.1) 2(1.65,-0.1)
  silkscreen extent -1.25,-1.38 2.98,0.15, body extent -2.2,-1.48 2.2,1.48, height 0.25
Harwin_M22-2511205 [mm] "Header, 2mm, 12x1, TH"
  rect 1.3x1.3 hole 0.8: 1(-11,0)
  round 1.3 hole 0.8: 2(-9,0) 3(-7,0) 4(-5,0) 5(-3,0) 6(-1,0) 7(1,0) 8(3,0) 9(5,0) 10(7,0) 11(9,0) 12(11,0)
  silkscreen extent -12,-1 12,1.3, body extent -12,-1 12,1, height 5
Harwin_M50-3630242 [mm] "Header, 1.27mm, 2x1, SMT"
  rrect15% 0.65x3 smd: 1(-0.635,1.5) 2(0.635,-1.5)
  body extent -1.27,-2.5 1.27,2.5, height 4.48
Label_650x200 [mil] "Thermal Transfer Label"
  round 1 on Mech13: 0(0,0)
  silkscreen extent -325,-100 325,100, body extent -325,-100 325,100, height 1
Mill-Max_3154-0-00-15-00-00-03-0 [mm] "PCB Pin, 0.46 Dia, TH"
  round 1.2 hole 0.66: 1(0,0)
  silkscreen extent -1,-1 1,1, body extent -0.41,-0.41 0.41,0.41, height 0.9
On-Shore_OSTVN04A150 [mm] "Terminal Block, 2.54mm, 4-pole, Brass, TH"
  rect 1.8x1.8 hole 1.3: 1(-3.81,0)
  round 1.8 hole 1.3: 2(-1.27,0) 3(1.27,0) 4(3.81,0)
  silkscreen extent -5.8,-3.4 5.5,3.4, body extent -5.5,-3.25 5.47,3.38, height 8.91
PN0080A-MFG [mm]
  rrect33% 1.5x0.3 smd paste+0 mask+0: 1(-6.7,4.75) 2(-6.7,4.25) 3(-6.7,3.75) 4(-6.7,3.25) 5(-6.7,2.75) 6(-6.7,2.25) 7(-6.7,1.75) 8(-6.7,1.25) 9(-6.7,0.75) 10(-6.7,0.25) 11(-6.7,-0.25) 12(-6.7,-0.75) 13(-6.7,-1.25) 14(-6.7,-1.75) 15(-6.7,-2.25) 16(-6.7,-2.75) 17(-6.7,-3.25) 18(-6.7,-3.75) 19(-6.7,-4.25) 20(-6.7,-4.75) 41(6.7,-4.75) 42(6.7,-4.25) 43(6.7,-3.75) 44(6.7,-3.25) 45(6.7,-2.75) 46(6.7,-2.25) 47(6.7,-1.75) 48(6.7,-1.25) 49(6.7,-0.75) 50(6.7,-0.25) 51(6.7,0.25) 52(6.7,0.75) 53(6.7,1.25) 54(6.7,1.75) 55(6.7,2.25) 56(6.7,2.75) 57(6.7,3.25) 58(6.7,3.75) 59(6.7,4.25) 60(6.7,4.75)
  rrect33% 0.3x1.5 smd paste+0 mask+0: 21(-4.75,-6.7) 22(-4.25,-6.7) 23(-3.75,-6.7) 24(-3.25,-6.7) 25(-2.75,-6.7) 26(-2.25,-6.7) 27(-1.75,-6.7) 28(-1.25,-6.7) 29(-0.75,-6.7) 30(-0.25,-6.7) 31(0.25,-6.7) 32(0.75,-6.7) 33(1.25,-6.7) 34(1.75,-6.7) 35(2.25,-6.7) 36(2.75,-6.7) 37(3.25,-6.7) 38(3.75,-6.7) 39(4.25,-6.7) 40(4.75,-6.7) 61(4.75,6.7) 62(4.25,6.7) 63(3.75,6.7) 64(3.25,6.7) 65(2.75,6.7) 66(2.25,6.7) 67(1.75,6.7) 68(1.25,6.7) 69(0.75,6.7) 70(0.25,6.7) 71(-0.25,6.7) 72(-0.75,6.7) 73(-1.25,6.7) 74(-1.75,6.7) 75(-2.25,6.7) 76(-2.75,6.7) 77(-3.25,6.7) 78(-3.75,6.7) 79(-4.25,6.7) 80(-4.75,6.7)
  silkscreen extent -6.82,-5.5 5.5,5.57, body extent -7.55,-7.55 7.55,7.55, height 0.25
PW0020A_N [mm] "TSOP, 20-Leads, Body 6.5x4.4mm, Pitch 0.65mm, IPC Medium Density"
  oval 1.4x0.45 smd: 1(-2.95,2.925) 2(-2.95,2.275) 3(-2.95,1.625) 4(-2.95,0.975) 5(-2.95,0.325) 6(-2.95,-0.325) 7(-2.95,-0.975) 8(-2.95,-1.625) 9(-2.95,-2.275) 10(-2.95,-2.925) 11(2.95,-2.925) 12(2.95,-2.275) 13(2.95,-1.625) 14(2.95,-0.975) 15(2.95,-0.325) 16(2.95,0.325) 17(2.95,0.975) 18(2.95,1.625) 19(2.95,2.275) 20(2.95,2.925)
  Top Overlay keep-out lines w0.2: -1.85,-3.3 1.85,-3.3
  silkscreen extent -3.5,-3.3 1.85,3.4, body extent -3.21,-3.25 3.21,3.25, height 1
Samtec_FTSH-105-01-x-DV-K [mm] "Header(Shrouded), 1.27mm, 5x2, SMT"
  rect 2.79x0.74 smd: 1(-2.035,2.54) 2(2.035,2.54) 3(-2.035,1.27) 4(2.035,1.27) 5(-2.035,0) 6(2.035,0) 7(-2.035,-1.27) 8(2.035,-1.27) 9(-2.035,-2.54) 10(2.035,-2.54)
  silkscreen extent -3.73,-3.48 3.73,3.48, body extent -2.92,-3.18 2.92,3.17, height 6.13
Samtec_MTMM-105-15-x-D-150 [mm] "Header, 2mm, 5x2, TH"
  rrect50% 1.4x1.4 hole 0.89: 1(-1,4)
  round 1.4 hole 0.89: 2(1,4) 3(-1,2) 4(1,2) 5(-1,0) 6(1,0) 7(-1,-2) 8(1,-2) 9(-1,-4) 10(1,-4)
  silkscreen extent -2.6,-5.1 2.1,5.1, body extent -1.97,-5 1.97,5, height 5.31
Samtec_PTT-103-01-x-S [mm] "Header, 2mm, 3x1, TH"
  rect 1.3x1.3 hole 0.81: 1(-2,0)
  round 1.3 hole 0.81: 2(0,0) 3(2,0)
  silkscreen extent -2.81,-0.99 2.81,1.3, body extent -3,-0.99 3,0.99, height 4.7
Samtec_TMM-102-01-F-S [mm] "Header, 2mm, 2x1, TH"
  rect 1.4x1.4 hole 0.89: 1(-1,0)
  round 1.4 hole 0.89: 2(1,0)
  silkscreen extent -2,-0.98 2,1.25, body extent -2,-0.99 2,0.99, height 4.71
SOD-323 [mm] "NXP recommended land pattern"
  rect 0.6x0.6 smd paste-0.05: 1(-1.1,0) 2(1.1,0)
  silkscreen extent -2.06,-0.86 1.53,0.86, body extent -1.3,-0.67 1.3,0.68, height 1.1
SOIC-8 [mm] "duplicate of SO-8.  SOIC, 8-Leads, Body 5.0x4.0mm (max), Pitch 1.27mm, IPC Medium Density"
  rrect17% 1.45x0.6 smd: 1(-2.725,1.905) 2(-2.725,0.635) 3(-2.725,-0.635) 4(-2.725,-1.905) 5(2.725,-1.905) 6(2.725,-0.635) 7(2.725,0.635) 8(2.725,1.905)
  silkscreen extent -3.5,-2.5 0.9,2.5, body extent -3,-2.45 3,2.45, height 1.63
SOT-23 [mm] "SOT23, 3-Leads, Body 2.9x1.3mm, Pitch 0.95mm, Lead Span 2.5mm, IPC Medium Density"
  rrect50% 1x0.6 smd: 1(-1.2,0.95) 2(-1.2,-0.95) 3(1.2,0)
  silkscreen extent -1.63,-1.5 0.7,1.5, body extent -1.16,-1.45 1.21,1.45, height 1
SOT-23L [mm] "SOT23, 3-Leads, Body 2.9x1.3mm, Pitch 0.95mm, Lead Span 2.5mm, IPC High Density"
  rrect50% 0.8x0.6 smd: 1(-1.1,0.95) 2(-1.1,-0.95) 3(1.1,0)
  silkscreen extent -1.5,-1.5 0.7,1.5, body extent -1.16,-1.45 1.21,1.45, height 1
TEC_282841-2 [mm] "TE Connectivity"
  rect 2.15x2.15 hole 1.4: 1(-2.54,0)
  round 2.15 hole 1.4: 2(2.54,0)
  silkscreen extent -5.9,-4.52 5.55,4.47, body extent -5.08,-4.52 5.58,4.48, height 15.2
TNPV1206 [mm] "VISHAY"
  rrect11% 0.9x1.7 smd: 1(-1.6,0) 2(1.6,0)
  silkscreen extent -2.4,-1.2 2.4,1.2, body extent -1.67,-0.87 1.67,0.87, height 0.65
WEEE_Minimum [mm] "WEEElie bin"
  silkscreen extent -2.42,-4.38 2.52,2.65
WL-SMCW_Green_0805 [mm] "SMD, 2-Leads, Body 2x1.25mm"
  rect 1.1x1.2 smd: 1(-1.05,0) 2(1.05,0)
  silkscreen extent -2.4,-1.1 1.5,1.1, body extent -1,-0.62 1,0.63, height 0.7
Wurth_61000218321 [mm] "Header, 2.54mm, 2x1, SMT"
  rect 1x3 smd: 1(-1.27,1.5) 2(1.27,-1.5)
  silkscreen extent -2.86,-1.27 2.54,1.27, body extent -2.54,-2.5 2.54,2.5, height 6.3
WURTH_61300111121 [mm] "Header, 2.54 mm, 1x1, TH"
  rect 1.65x1.65 hole 1.15: 1(0,0)
  silkscreen extent -1.27,-1.27 1.27,1.27, body extent -1.27,-1.27 1.27,1.27, height 8.54

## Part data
C1 C3: library part CMP-0093200-1, "1µF ±10% 10V Ceramic Capacitor X7R 0402 (1005 Metric)", Digikey Part Number=2571-GMC04X7R105K10NTTR-ND, Manufacturer="Cal-Chip Electronics", Operating Temperature Range="-55°C to +125°C", TempCo=15%, Temperature Characteristic=X7R, Tolerance_%=10%, ValueDisplayed=1uF
C2 C10: library part CMP-0006659-2, "CAP, CERM, 0.1 uF, 25 V, +/- 10%, X7R, 0402", Cap_Case=0402, Manufacturer=MuRata, Supplier Part Number 1=490-10698-1-ND, TempCo=X7R, Tolerance_%=10%, Value1=Unknown, Value2=25V, ValueDisplayed=0.1uF
C4 C5: library part CMP-0006439-2, "CAP, CERM, 22 pF, 50 V, +/- 5%, C0G/NP0, 0402", Cap_Case=0402, Manufacturer=MuRata, Supplier Part Number 1=81-GRM1555C1H220JA1D, TempCo=C0G/NP0, Tolerance_%=5%, Value1=Unknown, Value2=50V, ValueDisplayed=22pF
C6 C67: library part CMP-0006420-2, "CAP, CERM, 15 pF, 50 V, +/- 5%, C0G/NP0, 0402", Cap_Case=0402, Manufacturer=MuRata, Supplier Part Number 1=81-GRM1555C1H150JA1D, TempCo=C0G/NP0, Tolerance_%=5%, Value1=Unknown, Value2=50V, ValueDisplayed=15pF
C7 C8: library part CMP-0006200-2, "CAP, CERM, 100 pF, 16 V, +/- 10%, X7R, 0402", Cap_Case=0402, Manufacturer=AVX, Supplier Part Number 1=478-7887-1-ND, TempCo=X7R, Tolerance_%=10%, Value1=Unknown, Value2=16V, ValueDisplayed=100pF
C9 C62 C68: library part CMP-0006600-2, "CAP, CERM, 0.47 uF, 16 V, +/- 10%, X5R, 0402", Cap_Case=0402, Manufacturer=MuRata, TempCo=X5R, Tolerance_%=10%, Value1=Unknown, Value2=16V, ValueDisplayed=0.47uF
C29 C30 C34 C38 C54: library part CMP-0007392-5, "CAP, CERM, 0.033 uF, 16 V, +/- 10%, X7R, 0603", Cap_Case=0603, Manufacturer=MuRata, Supplier Part Number 1=490-1528-1-ND, TempCo=X7R, Tolerance_%=10%, Value1=Unknown, Value2=16V, ValueDisplayed=0.033uF
C31: library part CMP-0006802-4, "CAP, CERM, 0.1 uF, 50 V, +/- 10%, X7R, 0603", Cap_Case=0603, Manufacturer=AVX, Supplier Part Number 1=478-5052-1-ND, TempCo=X7R, Tolerance_%=10%, Value1=Unknown, Value2=50V, ValueDisplayed=0.1uF
C53: library part CMP-0006941-4, "CAP, CERM, 4700 pF, 100 V, +/- 5%, C0G/NP0, 0603", Cap_Case=0603, Manufacturer=Kemet, Supplier Part Number 1=399-9974-1-ND, TempCo=C0G/NP0, Tolerance_%=5%, Value1=Unknown, Value2=100V, ValueDisplayed=4700pF
C57: library part CMP-0860563-1, "CAP, CERM, 0.22 µF, 16 V,+/- 10%, X7R, 0402", Cap_Case=0402, Manufacturer="Samsung Electro-Mechanics", TempCo=X7R, Tolerance_%=10%, Value2=16V
C63: library part CMP-0006564-3, "CAP, CERM, 10 uF, 10 V, +/- 20%, X5R, 0402", Cap_Case=0402, Manufacturer=MuRata, TempCo=X5R, Tolerance_%=20%, Value1=Unknown, Value2=10V, ValueDisplayed=10uF
C64: library part CMP-0086061-1, "CAP, CERM, 1 µF, 25 V,+/- 10%, X5R, 0402", Cap_Case=0402, Manufacturer=MuRata, TempCo=X5R, Tolerance_%=10%, Value2=25V, ValueDisplayed=1µF
C66: library part CMP-0006560-2, "CAP, CERM, 1000 pF, 10 V, +/- 10%, X5R, 0402", Cap_Case=0402, Manufacturer=MuRata, Supplier Part Number 1=GRM155R61A102KA01D-ND, TempCo=X5R, Tolerance_%=10%, Value1=Unknown, Value2=10V, ValueDisplayed=1000pF
C80 C81: library part CMP-0006979-5, "CAP, CERM, 0.1 uF, 25 V, +/- 10%, X7R, 0603", Cap_Case=0603, Manufacturer=Kemet, Supplier Part Number 1=399-5345-1-ND, TempCo=X7R, Tolerance_%=10%, Value1=Unknown, Value2=25V, ValueDisplayed=0.1uF
C84 C85: library part CMP-0007069-4, "CAP, CERM, 10 pF, 50 V, +/- 5%, C0G/NP0, AEC-Q200 Grade 1, 0603", Cap_Case=0603, Manufacturer=TDK, Supplier Part Number 1=445-5628-1-ND, TempCo=C0G/NP0, Tolerance_%=5%, Value1=Unknown, Value2=50V, ValueDisplayed=10pF
C86: library part CMP-0007090-4, "CAP, CERM, 0.1 uF, 25 V, +/- 10%, X8R, AEC-Q200 Grade 0, 0603", Cap_Case=0603, Manufacturer=TDK, Supplier Part Number 1=445-5885-1-ND, TempCo=X8R, Tolerance_%=10%, Value1=Unknown, Value2=25V, ValueDisplayed=0.1uF
D1 D2: library part CMP-0002960-2, "LED, Bright Green, SMD", Color="Bright Green", Manufacturer="Wurth Elektronik", Power_TotalModule=72mW, Supplier Part Number 1=732-4986-1-ND, Value1=0.072W, Value2=2V
D3 D5 D13: library part CMP-0028455-2, "Diode, Schottky, 30 V, 0.2 A, SOD-323", Manufacturer="ON Semiconductor", Value1=0.2A, Value2=0.35V
D4 D9: library part CMP-0120648-1, "IR Emitter High Speed 850nm 50mW/sr 100mA 1.9V 2-Pin SMD T/R", Color=Infrared, Digikey Part Number=VSMY2853SLX01CT-ND, Forward Current=100mA, Manufacturer=Vishay, Mouser Part Number=78-VSMY2853SLX01, Operating Temperature Range="-40°C to +85°C", Power_TotalModule=190mW
D6 D7 D8 D10 D12 D14 D15 D16: library part CMP-0076968-2, "Diode, Switching, 70 V, 0.215 A, SOT-23", Manufacturer="Micro Commercial Components", Value1=0.215A, Value2=V
FID1 FID2 FID3: library part CMP-0077181-1, "Fiducial mark.  There is nothing to buy or mount.", Manufacturer=N/A
H1 H2: library part CMP-0079299-1, "3.5 mm PCB Hole", Manufacturer=Any
J1: library part CMP-0075634-2, "Header(Shrouded), 1.27mm, 5x2, Gold, SMT", Color=Black, Current_A=3.3A, Manufacturer=Samtec, Supplier Part Number 1=SAM8799-ND
J2: library part CMP-0109233-1, "2 Position Wire to Board Terminal Block Horizontal with Board 0.400\" (10.16mm) Through Hole", Current_A=14A, Digikey Part Number=732-11177-ND, Manufacturer="Wurth Electronics", Mouser Part Number=710-691216610002, Operating Temperature Range="-30°C to +120°C", Voltage_V=300V
J3 J12: library part CMP-0054787-1, "Header, 2.54mm, 2x1, Gold, SMT", Color=Black, Manufacturer="Wurth Elektronik"
J4: library part CMP-0079909-1, "Header, 1.27mm, 2x1, Gold with Tin tail, SMT", Color=Black, Current_A=1A, Manufacturer=Harwin, Supplier Part Number 1=952-3606-ND, Voltage_V=500V
J5 J6: library part CMP-0054792-1, "Header, 2.54 mm, 1x1, Gold, TH", Manufacturer="Wurth Elektronik", Supplier Part Number 1=732-5314-ND
J7 J8: library part CMP-0075238-1, "Header, 2mm, 12x1, Gold, TH", Color=Black, Current_A=1A, Manufacturer=Harwin, Supplier Part Number 1=M22-2511205-ND, Voltage_V=500V
J10: library part CMP-0055583-2, "Header, 2mm, 5x2, Gold, TH", Color=Black, Manufacturer=Samtec
J11: library part CMP-0075560-1, "Header, 2mm, 2x1, Gold, TH", Manufacturer=Samtec
J14: library part CMP-0054973-1, "Terminal Block, 2x1, 5.08mm, TH", Manufacturer="TE Connectivity", Supplier Part Number 1=A98342-ND
J15: library part CMP-0075095-1, "Terminal Block, 2.54mm, 4x1, Brass, TH", Manufacturer="On-Shore Technology", Supplier Part Number 1=ED10563-ND
J20: library part CMP-0055571-1, "Header, 2mm, 3x1, Gold, TH", Color=Black, Current_A=2.9A, Manufacturer=Samtec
